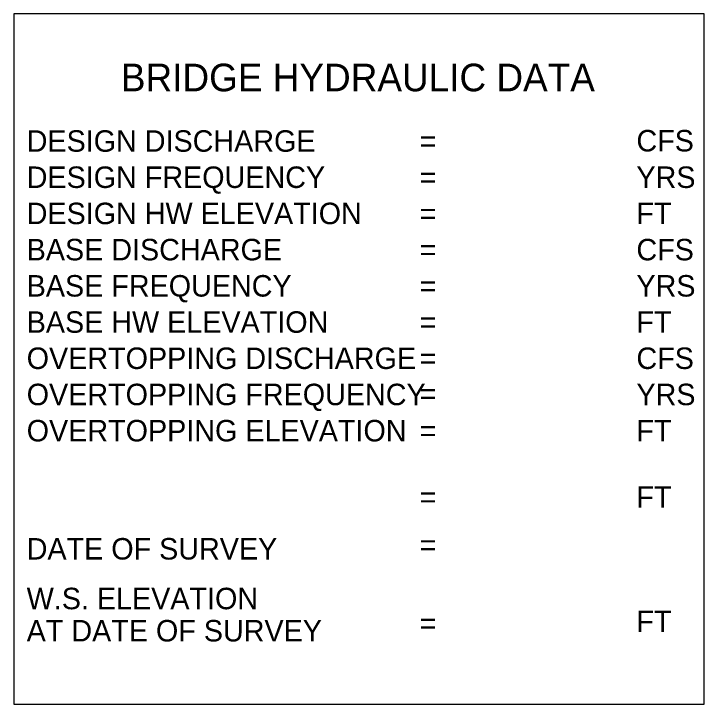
# Model space of a CAD drawing. Extents: x 10070 to 15319, y 8517 to 10343.
# Drawn here: x 15094.1 to 15319.1, y 9328.2 to 9553.2 of the extents above; entities that cross this region are included whole.
import ezdxf

# ---------------------------------------------------------------- set-up
doc = ezdxf.new("R2010")
doc.units = 0
doc.layers.add('Prop Grid Mask', color=7, linetype='Continuous')
doc.layers.add('Scratch_Level_4', color=7, linetype='Continuous')

msp = doc.modelspace()

# ---------------------------------------------------------------- linework, layer by layer
at = {"layer": 'Prop Grid Mask'}
msp.add_lwpolyline([(15094.14, 9328.15), (15319.14, 9328.15), (15319.14, 9553.15), (15094.14, 9553.15)], close=True, dxfattribs=at)

# ---------------------------------------------------------------- texts
at = {"layer": 'Scratch_Level_4'}
for s, height, p in [('BRIDGE HYDRAULIC DATA', 9, (15129.04, 9527.9)), ('DESIGN DISCHARGE', 7, (15098.34, 9508.2)), ('CFS', 7, (15297.06, 9508.3)), ('=         ', 7, (15226.41, 9508.2)), ('DESIGN FREQUENCY', 7, (15098.34, 9496.4)), ('YRS', 7, (15297.06, 9496.4)), ('=    ', 7, (15226.41, 9496.4)), ('DESIGN HW ELEVATION', 7, (15098.34, 9484.6)), ('FT', 7, (15297.06, 9484.6)), ('=         ', 7, (15226.41, 9484.6)), ('BASE DISCHARGE', 7, (15098.34, 9472.8)), ('CFS', 7, (15297.06, 9472.8)), ('=         ', 7, (15226.41, 9472.8)), ('BASE FREQUENCY', 7, (15098.34, 9461)), ('YRS', 7, (15297.06, 9461)), ('=    ', 7, (15226.41, 9461)), ('BASE HW ELEVATION', 7, (15098.34, 9449.2)), ('FT', 7, (15297.06, 9449.2)), ('=         ', 7, (15226.41, 9449.2)), ('OVERTOPPING DISCHARGE', 7, (15098.34, 9437.4)), ('CFS', 7, (15297.06, 9437.4)), ('=         ', 7, (15226.41, 9437.4)), ('OVERTOPPING FREQUENCY', 7, (15098.34, 9425.6)), ('YRS', 7, (15297.06, 9425.6)), ('=    ', 7, (15226.41, 9425.9)), ('OVERTOPPING ELEVATION', 7, (15098.34, 9413.8)), ('FT', 7, (15297.06, 9413.8)), ('=         ', 7, (15226.41, 9413.8)), ('FT', 7, (15297.06, 9392.2)), ('=         ', 7, (15226.41, 9392.2)), ('DATE OF SURVEY', 7, (15098.34, 9375.3)), ('=           ', 7, (15226.41, 9376.6)), ('W.S. ELEVATION', 7, (15098.34, 9359.1)), ('FT', 7, (15297.06, 9351.65)), ('AT DATE OF SURVEY', 7, (15098.34, 9348.6)), ('=         ', 7, (15226.41, 9351.05))]:
    msp.add_text(s, height=height, dxfattribs=at).set_placement(p)

doc.saveas('drawing.dxf')
